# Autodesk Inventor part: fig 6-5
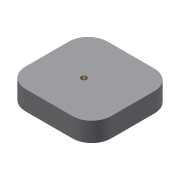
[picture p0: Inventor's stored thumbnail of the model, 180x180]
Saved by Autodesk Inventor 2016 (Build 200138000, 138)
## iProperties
Created: 2004-05
Part Number: fig 6-5
Document SubType Name: Modeling
Designer: CADCIM Technologies
Manufacturer: Standard
Standards Organization: Custom
Density: 1 g/cm^3
Material: Generic
Appearance: Default
Author: CADCIM Technologies
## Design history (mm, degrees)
sketch "Sketch1"
  geometry: L1 (0, 0)-(44.293, 0); L2 (44.293, 0)-(44.293, 42.442); L3 (44.293, 42.442)-(0, 42.442); L4 (0, 42.442)-(0, 0)
  constraints: 8 end point, 2 parallel, 1 horizontal, 1 perpendicular
extrude "Extrusion1" new body sketch "Sketch1" distance "d0" = 10; taper "d1" = 0 deg
fillet "Fillet1" dims "d2" = 10
sketch "Sketch2"
  geometry: 1 further point
sketch "Sketch3"
  geometry: L1 (10, 42.442)-(34.293, 42.442) reference; L2 (0, 10)-(0, 32.442) reference; L3 (34.293, 0)-(10, 0) reference; L4 (44.293, 32.442)-(44.293, 10) reference; A1 r 10 centre (34.293, 32.442) between (44.293, 32.442) and (34.293, 42.442) reference; A2 r 10 centre (10, 32.442) between (10, 42.442) and (0, 32.442) reference; A3 r 10 centre (10, 10) between (0, 10) and (10, 0) reference; A4 r 10 centre (34.293, 10) between (34.293, 0) and (44.293, 10) reference; 1 further point
workaxis "Work Axis1"
  workpoint "Work Point1"
hole "Hole3" diameter "d24" = 3; stored, may be unused: countersink angle "d28" = 90 deg, drill point angle "d30" = 118 deg; dims "d22" = 10, "d23" = 10, "d25" = 6, "d26" = 4, "d27" = 2, "d29" = 8
body "Solid1"
